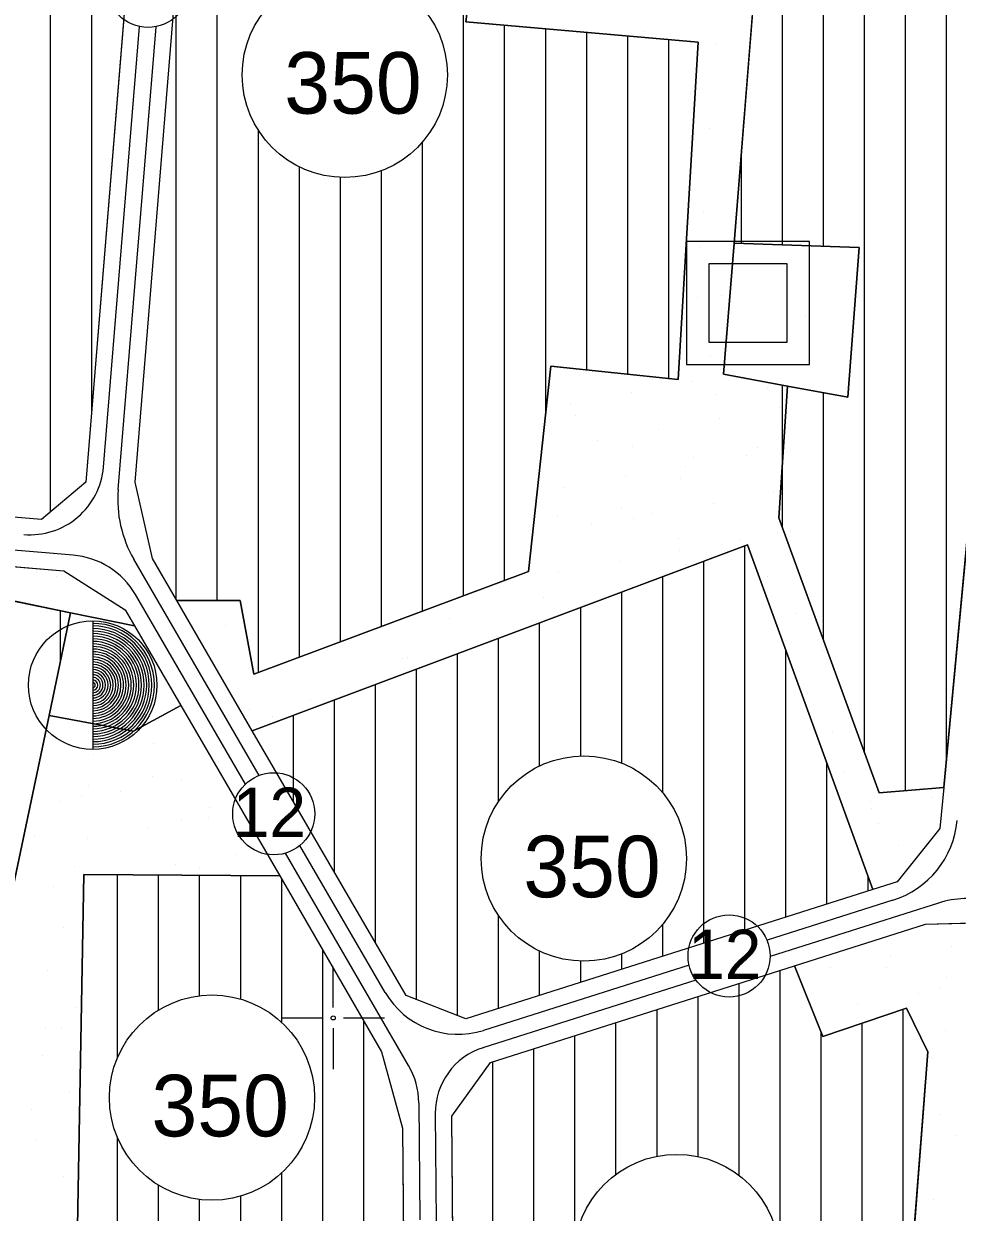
# Model space of a CAD drawing. Extents: x 419109 to 421295, y 4452223 to 4457798.
# Drawn here: x 420924.6 to 421152, y 4452952.7 to 4453242.2 of the extents above; entities that cross this region are included whole.
import ezdxf

# ---------------------------------------------------------------- set-up
doc = ezdxf.new("R2010")
doc.units = 0
for name, color, linetype in [('ADA', 7, 'Continuous'), ('ADAKENARI', 7, 'Continuous'), ('Default', 7, 'Continuous'), ('KALDIRIM', 7, 'Continuous'), ('KD_DAIRE', 7, 'Continuous'), ('KD_YGEN', 7, 'Continuous'), ('LJ_SEMBOL', 7, 'Continuous'), ('PAFTALAMA', 7, 'Continuous'), ('PL_AYA_PARK_DINLENME', 7, 'Continuous'), ('PL_K_YONETIM', 7, 'Continuous'), ('PL_KON_MEV_350', 7, 'Continuous'), ('PL_OZEL_DONATI', 7, 'Continuous'), ('SM_DAIRE', 7, 'Continuous'), ('SM_TAKS', 7, 'Continuous'), ('TR_ORTAYOGUNKONUT', 7, 'Continuous'), ('TR_PARKALANI', 7, 'Continuous'), ('TR_SAGLIKTESIS', 7, 'Continuous')]:
    doc.layers.add(name, color=color, linetype=linetype)

# ---------------------------------------------------------------- blocks, each defined once
blk = doc.blocks.new('POINT_DISPLAY')
at = {"layer": 'Default'}
blk.add_line((0, 0), (0, 0), dxfattribs=at)

msp = doc.modelspace()

# ---------------------------------------------------------------- linework, layer by layer
at = {"layer": 'ADA'}
for p, q in [((421097.65, 4453188.75), (421103.84, 4453266.28)), ((421032.34, 4453242.63), (421088.94, 4453237.73)), ((421088.94, 4453237.73), (421084.04, 4453155.55)), ((421095.1, 4453156.8), (421097.65, 4453188.75)), ((421128.13, 4453187.66), (421097.65, 4453188.75)), ((421125.41, 4453151.19), (421128.13, 4453187.66)), ((421053.02, 4453158.81), (421047.58, 4453108.74)), ((421084.04, 4453155.55), (421053.02, 4453158.81)), ((421095.1, 4453156.8), (421110.71, 4453153.91)), ((421108.54, 4453121.8), (421110.71, 4453153.91)), ((421110.71, 4453153.91), (421125.41, 4453151.19)), ((421133.03, 4453054.85), (421108.54, 4453121.8)), ((420936.03, 4453098.7), (420853.73, 4453115.66)), ((420980.29, 4453069.97), (421100.92, 4453115.27)), ((421100.92, 4453115.27), (421131.45, 4453031.3)), ((421047.58, 4453108.74), (420980.63, 4453083.7)), ((420977.36, 4453101.66), (420961.9, 4453101.66)), ((420980.63, 4453083.7), (420977.36, 4453101.66)), ((420930.77, 4453073.67), (420936.03, 4453098.7)), ((420951.61, 4453095.49), (420936.03, 4453098.7)), ((420962.86, 4453076.1), (420951.34, 4453069.86)), ((420903.28, 4452943.11), (420930.77, 4453073.67)), ((420951.34, 4453069.86), (420930.77, 4453073.67)), ((421148.76, 4453056.16), (421133.03, 4453054.85)), ((420939.24, 4453034.97), (420937.46, 4452935.63)), ((420986.96, 4453034.57), (420939.24, 4453034.97)), ((421112.39, 4453012.66), (421119.28, 4452995.43)), ((421119.28, 4452995.43), (421139.68, 4453002.38)), ((421139.68, 4453002.38), (421144.89, 4452991.74)), ((421144.89, 4452991.74), (421136.89, 4452888.88))]:
    msp.add_line(p, q, dxfattribs=at)
at = {"layer": 'ADAKENARI'}
for p, q in [((421175.98, 4453346.49), (421148.76, 4453056.16)), ((420949.41, 4453248.8), (420939.72, 4453130.53)), ((420951.76, 4453130.52), (420961.37, 4453247.82)), ((420928.94, 4453121.4), (420750.67, 4453136.33)), ((420939.72, 4453130.53), (420928.94, 4453121.4)), ((420955.96, 4453111.91), (420951.76, 4453130.52)), ((420853.73, 4453115.66), (420934.35, 4453108.91)), ((420961.9, 4453101.66), (420955.96, 4453111.91)), ((420934.35, 4453108.91), (420949.33, 4453099.42)), ((420980.29, 4453069.97), (420961.9, 4453101.66)), ((420949.33, 4453099.42), (420951.61, 4453095.49)), ((420951.61, 4453095.49), (420962.86, 4453076.1)), ((420962.86, 4453076.1), (420986.96, 4453034.57)), ((421017.74, 4453005.42), (420980.29, 4453069.97)), ((421148.76, 4453056.16), (421147.82, 4453046.17)), ((421147.82, 4453046.17), (421137.36, 4453033.18)), ((420986.96, 4453034.57), (421011.8, 4452991.75)), ((421131.45, 4453031.3), (421032.29, 4452999.8)), ((421137.36, 4453033.18), (421131.45, 4453031.3)), ((421112.39, 4453012.66), (421144.3, 4453022.8)), ((421144.3, 4453022.8), (421163.52, 4453023.36)), ((421038.32, 4452989.12), (421112.39, 4453012.66)), ((421032.29, 4452999.8), (421017.74, 4453005.42)), ((421011.8, 4452991.75), (421016.9, 4452973.1)), ((421028.88, 4452976.1), (421038.32, 4452989.12)), ((421029.52, 4452898.03), (421028.88, 4452976.1)), ((421016.9, 4452973.1), (421017.2, 4452936.24))]:
    msp.add_line(p, q, dxfattribs=at)
at = {"layer": 'KALDIRIM'}
for p, q in [((420944.03, 4453134.2), (420952.83, 4453241.5)), ((420947.6, 4453128.7), (420956.84, 4453241.48)), ((420936.62, 4453112.73), (420836.13, 4453121.15)), ((420981.99, 4453059.07), (420951.42, 4453111.76)), ((420978.6, 4453056.94), (420951.81, 4453103.12)), ((421012.66, 4453006.22), (420991.89, 4453042.01)), ((421018.37, 4452988.4), (420988.36, 4453040.13)), ((421136.37, 4453028.67), (421105.68, 4453018.92)), ((421147.43, 4453027.99), (421106.44, 4453014.96)), ((421086.69, 4453012.88), (421036.59, 4452996.97)), ((421088.35, 4453009.21), (421036.49, 4452992.74)), ((421020.85, 4452979.33), (421021.08, 4452950.8)), ((421024.87, 4452976.71), (421025.09, 4452950.39))]:
    msp.add_line(p, q, dxfattribs=at)
for centre, radius, start, end in [((420926.11, 4453135.67), 17.98, 265.212, 355.3151), ((420976.54, 4453126.33), 29.04, 175.3151, 210.1219), ((420935, 4453093.37), 19.43, 30.1219, 85.212), ((421129.52, 4453050.21), 22.6, 287.6274, 354.6441), ((421154.41, 4453006.03), 23.04, 75.7392, 107.6274), ((421030.39, 4453016.5), 20.5, 210.1219, 287.6274), ((421041.54, 4452976.85), 16.67, 107.6274, 180.4725), ((421002.47, 4452979.18), 18.38, 0.4725, 30.1219)]:
    msp.add_arc(centre, radius, start, end, dxfattribs=at)
at = {"layer": 'KD_DAIRE'}
for centre in [(420954.89, 4453251.29), (420985.51, 4453049.72), (421096.44, 4453015.09)]:
    msp.add_circle(centre, 10, dxfattribs=at)
at = {"layer": 'LJ_SEMBOL'}
for p, q in [((421116.04, 4453189.14), (421086.04, 4453189.14)), ((421086.04, 4453189.14), (421086.04, 4453159.14)), ((421116.04, 4453159.14), (421116.04, 4453189.14)), ((421110.58, 4453183.69), (421091.49, 4453183.69)), ((421091.49, 4453183.69), (421091.49, 4453164.6)), ((421110.58, 4453164.6), (421110.58, 4453183.69)), ((421091.49, 4453164.6), (421110.58, 4453164.6)), ((421086.04, 4453159.14), (421116.04, 4453159.14)), ((420941.4, 4453096.75), (420941.4, 4453065.42))]:
    msp.add_line(p, q, dxfattribs=at)
msp.add_lwpolyline([(421086.04, 4453159.14), (421116.04, 4453159.14), (421116.04, 4453189.14), (421086.04, 4453189.14)], close=True, dxfattribs=at)
msp.add_circle((420941.4, 4453081.08), 15.66, dxfattribs=at)
for radius in [15.04, 14.41, 13.78, 13.16, 12.53, 11.9, 11.28, 10.65, 10.02, 9.4, 8.77, 8.14, 7.52, 6.89, 6.26, 5.64, 5.01, 4.39, 3.76, 3.13, 2.51, 1.88, 1.25, 0.627]:
    msp.add_arc((420941.4, 4453081.08), radius, 270, 90, dxfattribs=at)
at = {"layer": 'PAFTALAMA'}
for p, q in [((421000, 4453002.5), (421000, 4453012.5)), ((420987.5, 4453000), (420997.5, 4453000)), ((421002.5, 4453000), (421012.5, 4453000)), ((421000, 4452997.5), (421000, 4452987.5))]:
    msp.add_line(p, q, dxfattribs=at)
msp.add_circle((421000, 4453000), 0.5, dxfattribs=at)
at = {"layer": 'PL_AYA_PARK_DINLENME'}
for points in [[(421047.58, 4453108.74), (421053.02, 4453158.81), (421084.04, 4453155.55), (421088.94, 4453237.73), (421032.34, 4453242.63), (421041.04, 4453310.67), (421052.47, 4453314.48), (421058.89, 4453263.75), (421079.47, 4453263.3), (421103.84, 4453266.28), (421097.65, 4453188.75), (421095.1, 4453156.8), (421110.71, 4453153.91), (421108.54, 4453121.8), (421133.03, 4453054.85), (421148.76, 4453056.16), (421147.82, 4453046.17), (421137.36, 4453033.18), (421131.45, 4453031.3), (421100.92, 4453115.27), (420980.29, 4453069.97), (420961.9, 4453101.66), (420977.36, 4453101.66), (420980.63, 4453083.7)], [(420936.03, 4453098.7), (420853.73, 4453115.66), (420934.35, 4453108.91), (420949.33, 4453099.42), (420951.61, 4453095.49)], [(420903.28, 4452943.11), (420930.77, 4453073.67), (420951.34, 4453069.86), (420962.86, 4453076.1), (420986.96, 4453034.57), (420939.24, 4453034.97), (420937.46, 4452935.63)], [(421166.65, 4452960.6), (421161.92, 4452889.08), (421136.89, 4452888.88), (421144.89, 4452991.74), (421139.68, 4453002.38), (421119.28, 4452995.43), (421112.39, 4453012.66), (421144.3, 4453022.8), (421163.52, 4453023.36), (421170.69, 4453021.54)]]:
    msp.add_lwpolyline(points, close=True, dxfattribs=at)
at = {"layer": 'PL_K_YONETIM'}
msp.add_lwpolyline([(420951.34, 4453069.86), (420930.77, 4453073.67), (420936.03, 4453098.7), (420951.61, 4453095.49), (420962.86, 4453076.1)], close=True, dxfattribs=at)
at = {"layer": 'PL_KON_MEV_350'}
for points in [[(420948.86, 4453560.69), (420947.43, 4453390.26), (420929.47, 4453297.28), (420949.35, 4453291.43), (420949.88, 4453263.97), (420949.91, 4453262.07), (420949.91, 4453260.17), (420949.89, 4453258.28), (420949.84, 4453256.38), (420949.77, 4453254.48), (420949.67, 4453252.59), (420949.55, 4453250.69), (420949.41, 4453248.8), (420939.72, 4453130.53), (420928.94, 4453121.4), (420750.67, 4453136.33)], [(421103.84, 4453266.28), (421097.65, 4453188.75), (421128.13, 4453187.66), (421125.41, 4453151.19), (421110.71, 4453153.91), (421108.54, 4453121.8), (421133.03, 4453054.85), (421148.76, 4453056.16), (421175.98, 4453346.49)]]:
    msp.add_lwpolyline(points, dxfattribs=at)
for points in [[(420961.24, 4453297.08), (421041.04, 4453310.67), (421032.34, 4453242.63), (421088.94, 4453237.73), (421084.04, 4453155.55), (421053.02, 4453158.81), (421047.58, 4453108.74), (420980.63, 4453083.7), (420977.36, 4453101.66), (420961.9, 4453101.66), (420955.96, 4453111.91), (420951.76, 4453130.52), (420961.37, 4453247.82), (420961.53, 4453249.86), (420961.65, 4453251.91), (420961.76, 4453253.96), (420961.83, 4453256), (420961.88, 4453258.05), (420961.91, 4453260.1), (420961.91, 4453262.15), (420961.88, 4453264.2)], [(420853.73, 4453115.66), (420936.03, 4453098.7), (420930.77, 4453073.67), (420903.28, 4452943.11), (420896.71, 4452915.75), (420797.89, 4452939.65), (420762.79, 4452946.51), (420739.04, 4452945.34), (420737.61, 4452949.84), (420736.39, 4452954.4), (420735.38, 4452959.01), (420734.6, 4452963.67), (420734.03, 4452968.36), (420733.69, 4452973.07), (420733.57, 4452977.79), (420733.67, 4452982.51), (420778.66, 4453027.49), (420837.05, 4453013.96), (420840.26, 4453053.48), (420782.22, 4453058.47), (420778.66, 4453027.49), (420733.67, 4452982.51), (420739.7, 4453115.18), (420750.12, 4453124.34)], [(420980.29, 4453069.97), (421100.92, 4453115.27), (421131.45, 4453031.3), (421032.29, 4452999.8), (421017.74, 4453005.42)], [(421011.8, 4452991.75), (421016.9, 4452973.1), (421017.2, 4452936.24), (420937.46, 4452935.63), (420939.24, 4453034.97), (420986.96, 4453034.57)], [(421144.89, 4452991.74), (421136.89, 4452888.88), (421039.6, 4452888.11), (421029.52, 4452898.03), (421028.88, 4452976.1), (421038.32, 4452989.12), (421112.39, 4453012.66), (421119.28, 4452995.43), (421139.68, 4453002.38)]]:
    msp.add_lwpolyline(points, close=True, dxfattribs=at)
at = {"layer": 'PL_OZEL_DONATI'}
msp.add_lwpolyline([(421128.13, 4453187.66), (421125.41, 4453151.19), (421110.71, 4453153.91), (421095.1, 4453156.8), (421097.65, 4453188.75)], close=True, dxfattribs=at)
at = {"layer": 'SM_DAIRE'}
for centre in [(421002.82, 4453229.73), (421061.06, 4453038.82), (420970.46, 4452980.58), (421083.71, 4452941.75)]:
    msp.add_circle(centre, 25, dxfattribs=at)
at = {"layer": 'TR_ORTAYOGUNKONUT'}
for p, q in [((421139.43, 4453055.39), (421139.43, 4453361.18)), ((421149.43, 4453063.3), (421149.43, 4453360.27)), ((421031.76, 4453102.82), (421031.76, 4453309.09)), ((420931.16, 4453123.28), (420931.16, 4453296.78)), ((420971.76, 4453101.66), (420971.76, 4453298.87)), ((420941.16, 4453148.09), (420941.16, 4453293.84)), ((421109.43, 4453188.33), (421109.43, 4453273.16)), ((421119.43, 4453187.97), (421119.43, 4453272.5)), ((421129.43, 4453064.69), (421129.43, 4453271.84)), ((420961.76, 4453101.91), (420961.76, 4453254)), ((421041.76, 4453106.56), (421041.76, 4453241.82)), ((421051.76, 4453147.22), (421051.76, 4453240.95)), ((421061.76, 4453157.89), (421061.76, 4453240.08)), ((421071.76, 4453156.84), (421071.76, 4453239.22)), ((421081.76, 4453155.79), (421081.76, 4453238.35)), ((420981.76, 4453084.12), (420981.76, 4453216.26)), ((421021.76, 4453099.08), (421021.76, 4453213.42)), ((421099.43, 4453188.68), (421099.43, 4453211.04)), ((420991.76, 4453087.86), (420991.76, 4453207.31)), ((421001.76, 4453091.6), (421001.76, 4453204.75)), ((421011.76, 4453095.34), (421011.76, 4453206.39)), ((421109.43, 4453119.36), (421109.43, 4453154.15)), ((421119.43, 4453092.02), (421119.43, 4453152.3)), ((421100.29, 4453021.4), (421100.29, 4453115.03)), ((421090.29, 4453018.23), (421090.29, 4453111.28)), ((421080.29, 4453054.79), (421080.29, 4453107.52)), ((421070.29, 4453062.06), (421070.29, 4453103.77)), ((421060.29, 4453063.81), (421060.29, 4453100.01)), ((420933.57, 4453086.99), (420933.57, 4453099.21)), ((421050.29, 4453061.38), (421050.29, 4453096.26)), ((421040.29, 4453052.74), (421040.29, 4453092.5)), ((421030.29, 4453000.57), (421030.29, 4453088.74)), ((421110.29, 4453024.58), (421110.29, 4453089.48)), ((421020.29, 4453004.43), (421020.29, 4453084.99)), ((421010.29, 4453018.26), (421010.29, 4453081.23)), ((421000.29, 4453035.49), (421000.29, 4453077.48)), ((420990.29, 4453052.73), (420990.29, 4453073.72)), ((421120.29, 4453027.76), (421120.29, 4453061.98)), ((420947.46, 4452990.38), (420947.46, 4453034.9)), ((420957.46, 4453001.93), (420957.46, 4453034.81)), ((420967.46, 4453005.4), (420967.46, 4453034.73)), ((420977.46, 4453004.58), (420977.46, 4453034.65)), ((420987.46, 4452998.91), (420987.46, 4453033.7)), ((421130.29, 4453030.94), (421130.29, 4453034.48)), ((421040.29, 4453002.34), (421040.29, 4453024.9)), ((421080.29, 4453015.05), (421080.29, 4453022.85)), ((420997.46, 4452936.08), (420997.46, 4453016.47)), ((421050.29, 4453005.52), (421050.29, 4453016.26)), ((421060.29, 4453008.69), (421060.29, 4453013.83)), ((421070.29, 4453011.87), (421070.29, 4453015.59)), ((421108.88, 4452888.66), (421108.88, 4453011.54)), ((421098.88, 4452961.62), (421098.88, 4453008.36)), ((421088.88, 4452966.21), (421088.88, 4453005.19)), ((421078.88, 4452966.28), (421078.88, 4453002.01)), ((421138.88, 4452914.48), (421138.88, 4453002.11)), ((421007.46, 4452936.16), (421007.46, 4452999.23)), ((421068.88, 4452961.87), (421068.88, 4452998.83)), ((421128.88, 4452888.82), (421128.88, 4452998.7)), ((421058.88, 4452944.63), (421058.88, 4452995.65)), ((421118.88, 4452888.74), (421118.88, 4452996.43)), ((421048.88, 4452888.19), (421048.88, 4452992.48)), ((421038.88, 4452888.83), (421038.88, 4452989.3)), ((420947.46, 4452935.7), (420947.46, 4452970.78)), ((420987.46, 4452936.01), (420987.46, 4452962.25)), ((420957.46, 4452935.78), (420957.46, 4452959.23)), ((420967.46, 4452935.86), (420967.46, 4452955.76)), ((420977.46, 4452935.93), (420977.46, 4452956.58))]:
    msp.add_line(p, q, dxfattribs=at)

# ---------------------------------------------------------------- block references
at = {"layer": 'TR_PARKALANI', "xscale": 0.1, "yscale": 0.10000000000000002}
for p in [(421056.94, 4453240.99), (421075.49, 4453240.24), (421093.14, 4453237.22), (421099.8, 4453228.24), (421091.69, 4453216.66), (421098.35, 4453207.68), (421098.37, 4453208.29), (421090.24, 4453196.09), (421098.09, 4453195.64), (421089.48, 4453187.77), (421096.9, 4453187.11), (421088.79, 4453175.53), (421094.62, 4453175.94), (421095.45, 4453166.55), (421092.01, 4453161.17), (421087.34, 4453154.96), (421072.56, 4453152.36), (421105.92, 4453153.64), (421057.79, 4453149.75), (421093.44, 4453151.94), (421059, 4453146.68), (421108.77, 4453148.59), (421079.22, 4453143.38), (421094, 4453145.98), (421064.45, 4453140.77), (421072.9, 4453139.16), (421103.31, 4453138.87), (421087.67, 4453136.55), (421100.66, 4453137), (421071.11, 4453131.79), (421085.88, 4453134.4), (421056.34, 4453129.19), (421084.55, 4453131.42), (421107.32, 4453128.02), (421070.3, 4453124.38), (421092.55, 4453125.42), (421054.66, 4453122.06), (421063, 4453120.21), (421073.05, 4453121.78), (421077.77, 4453122.81), (421084.2, 4453116.86), (421099.21, 4453116.44), (421084.43, 4453113.83), (421054.89, 4453108.63), (421069.66, 4453111.23), (420927.6, 4453108.51), (420932.6, 4453107.47), (421105.87, 4453107.46), (421051.18, 4453102.37), (420934.26, 4453099.53), (420939.57, 4453099.45), (421028.32, 4453097.3), (421112.53, 4453098.48), (420973.85, 4453095.7), (421110.27, 4453091.95), (421119.19, 4453089.5), (421016.83, 4453087.66), (421018.17, 4453087.88), (420972.92, 4453084.02), (420981, 4453083.69), (420994.35, 4453077.64), (421115.45, 4453079.03), (420979.58, 4453075.04), (420958.66, 4453073.6), (420985.15, 4453073.4), (421121.57, 4453069.65), (420956.3, 4453066.83), (420941.53, 4453064.22), (421124.4, 4453059.96), (420940.41, 4453056.5), (420956.05, 4453058.82), (420962.96, 4453057.85), (420938.79, 4453054.01), (420948.19, 4453055.24), (421145.83, 4453053.58), (420933.42, 4453052.64), (420969.96, 4453051.29), (421130.91, 4453052.83), (421131.06, 4453050.98), (420963.14, 4453048.33), (420969.62, 4453048.87), (420954.85, 4453046.26), (421132.87, 4453047.35), (420927.3, 4453044.37), (420940.08, 4453043.66), (421137.72, 4453042), (420925.31, 4453041.05), (420976.28, 4453039.89), (420936.94, 4453036.81), (420961.51, 4453037.28), (420967.35, 4453036.52), (420931.97, 4453032.08), (420934.34, 4453022.04), (420938.63, 4453023.1), (421150.64, 4453017.48), (421135.87, 4453014.87), (420930.51, 4453011.51), (421121.09, 4453012.27), (421134.75, 4453012.36), (421147.9, 4453007.27), (421149.52, 4453009.76), (421142.53, 4453005.89), (420937.18, 4453002.53), (421127.75, 4453003.29), (420930, 4452997.42), (420933.86, 4452997.66), (421149.19, 4452996.91), (420929.06, 4452990.95), (421146.05, 4452990.06), (420935.72, 4452981.97), (420926.52, 4452977.72), (421147.74, 4452976.35), (420927.61, 4452970.38), (421151.86, 4452971.43), (420934.27, 4452961.4), (420937.82, 4452961.82), (421146.28, 4452955.79)]:
    msp.add_blockref('POINT_DISPLAY', p, dxfattribs=at)
at = {"layer": 'TR_SAGLIKTESIS', "xscale": 0.1, "yscale": 0.10000000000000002}
msp.add_blockref('POINT_DISPLAY', (421115.1, 4453171.19), dxfattribs=at)

# ---------------------------------------------------------------- texts
at = {"layer": 'KD_YGEN'}
for p in [(420975.54, 4453044.1), (421086.47, 4453009.47)]:
    msp.add_text('12', height=12, dxfattribs=at).set_placement(p)
at = {"layer": 'SM_TAKS'}
for p in [(420988.08, 4453220.29), (421046.32, 4453029.38), (420955.72, 4452971.14)]:
    msp.add_text('350', height=15, dxfattribs=at).set_placement(p)

doc.saveas('drawing.dxf')
